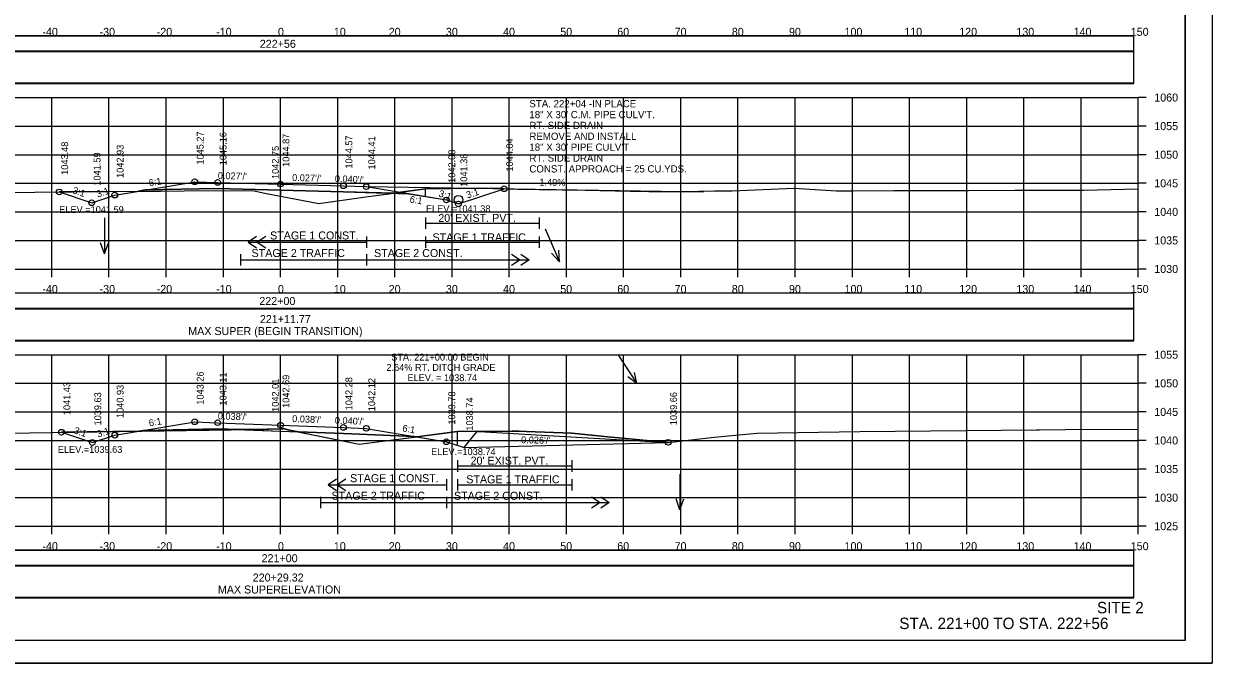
# Model space of a CAD drawing. Extents: x 1370565 to 1374448, y 301010 to 304637.
# Drawn here: x 1373323.9 to 1373531.7, y 303005 to 303116.9 of the extents above; entities that cross this region are included whole.
import ezdxf

# ---------------------------------------------------------------- set-up
doc = ezdxf.new("R2010")
doc.units = 0
for name, color, linetype in [('Default', 7, 'Continuous'), ('R_Alt Surface', 7, 'Continuous'), ('R_Axis', 7, 'Continuous'), ('R_Axis Annot', 7, 'Continuous'), ('R_Border', 7, 'Continuous'), ('R_Contours', 7, 'Continuous'), ('R_Draft', 7, 'Continuous'), ('R_Drive', 7, 'Continuous'), ('R_Exist Surface', 7, 'Continuous'), ('R_Fin Surface', 7, 'Continuous'), ('R_Grid', 7, 'Continuous'), ('R_No Plot', 7, 'Continuous'), ('R_Water', 7, 'Continuous'), ('R_Water Annot', 7, 'Continuous'), ('R_Xsect Elev', 7, 'Continuous'), ('R_Xsect Slope', 7, 'Continuous')]:
    doc.layers.add(name, color=color, linetype=linetype)

msp = doc.modelspace()

# ---------------------------------------------------------------- linework, layer by layer
at = {"layer": 'Default'}
for points in [[(1373219.61, 303112.04), (1373518.02, 303112.04), (1373518.02, 303114.75), (1373219.61, 303114.75)], [(1373219.61, 303106.46), (1373518.02, 303106.46), (1373518.02, 303111.99), (1373219.61, 303111.99)], [(1373219.61, 303067.04), (1373518.02, 303067.04), (1373518.02, 303069.75), (1373219.61, 303069.75)], [(1373219.61, 303061.46), (1373518.02, 303061.46), (1373518.02, 303066.99), (1373219.61, 303066.99)], [(1373219.61, 303022.04), (1373518.02, 303022.04), (1373518.02, 303024.75), (1373219.61, 303024.75)], [(1373219.61, 303016.46), (1373518.02, 303016.46), (1373518.02, 303021.99), (1373219.61, 303021.99)]]:
    msp.add_lwpolyline(points, close=True, dxfattribs=at)
at = {"layer": 'R_Alt Surface'}
for points in [[(1373345.15, 303087.83), (1373357.81, 303088.08), (1373368.81, 303087.78), (1373379.81, 303087.49), (1373391.18, 303087.18)], [(1373364.62, 303079.69), (1373363.12, 303078.69), (1373364.62, 303077.69)], [(1373366.22, 303079.69), (1373364.72, 303078.69), (1373366.22, 303077.69)], [(1373363.12, 303078.69), (1373383.82, 303078.69)], [(1373361.82, 303076.62), (1373361.82, 303074.62)], [(1373361.82, 303075.62), (1373383.82, 303075.62)], [(1373383.82, 303076.62), (1373383.82, 303074.62)], [(1373383.82, 303076.62), (1373383.82, 303074.62)], [(1373383.82, 303075.62), (1373412.31, 303075.62)], [(1373409.22, 303076.62), (1373410.72, 303075.62), (1373409.22, 303074.62)], [(1373410.81, 303076.62), (1373412.31, 303075.62), (1373410.81, 303074.62)], [(1373344.85, 303045.77), (1373357.81, 303046.03), (1373368.81, 303045.61), (1373379.81, 303045.19), (1373392.17, 303044.72)], [(1373378.61, 303037.23), (1373377.11, 303036.23), (1373378.61, 303035.23)], [(1373377.11, 303036.23), (1373397.81, 303036.23)], [(1373380.21, 303037.23), (1373378.71, 303036.23), (1373380.21, 303035.23)], [(1373375.81, 303034.15), (1373375.81, 303032.15)], [(1373397.81, 303034.15), (1373397.81, 303032.15)], [(1373397.81, 303034.15), (1373397.81, 303032.15)], [(1373423.21, 303034.15), (1373424.71, 303033.15), (1373423.21, 303032.15)], [(1373424.8, 303034.15), (1373426.3, 303033.15), (1373424.8, 303032.15)], [(1373375.81, 303033.15), (1373397.81, 303033.15)], [(1373397.81, 303033.15), (1373426.3, 303033.15)]]:
    msp.add_lwpolyline(points, dxfattribs=at)
at = {"layer": 'R_Axis'}
for p, q in [((1373518.81, 303074), (1373518.81, 303104)), ((1373520.21, 303104), (1373518.81, 303104)), ((1373520.21, 303099), (1373518.81, 303099)), ((1373520.21, 303094), (1373518.81, 303094)), ((1373520.21, 303089), (1373518.81, 303089)), ((1373520.21, 303084), (1373518.81, 303084)), ((1373520.21, 303079), (1373518.81, 303079)), ((1373218.81, 303074), (1373518.81, 303074)), ((1373328.81, 303072.6), (1373328.81, 303074)), ((1373338.81, 303072.6), (1373338.81, 303074)), ((1373348.81, 303072.6), (1373348.81, 303074)), ((1373358.81, 303072.6), (1373358.81, 303074)), ((1373368.81, 303072.6), (1373368.81, 303074)), ((1373378.81, 303072.6), (1373378.81, 303074)), ((1373388.81, 303072.6), (1373388.81, 303074)), ((1373398.81, 303072.6), (1373398.81, 303074)), ((1373408.81, 303072.6), (1373408.81, 303074)), ((1373418.81, 303072.6), (1373418.81, 303074)), ((1373428.81, 303072.6), (1373428.81, 303074)), ((1373438.81, 303072.6), (1373438.81, 303074)), ((1373448.81, 303072.6), (1373448.81, 303074)), ((1373458.81, 303072.6), (1373458.81, 303074)), ((1373468.81, 303072.6), (1373468.81, 303074)), ((1373478.81, 303072.6), (1373478.81, 303074)), ((1373488.81, 303072.6), (1373488.81, 303074)), ((1373498.81, 303072.6), (1373498.81, 303074)), ((1373508.81, 303072.6), (1373508.81, 303074)), ((1373518.81, 303072.6), (1373518.81, 303074)), ((1373520.21, 303074), (1373518.81, 303074)), ((1373518.81, 303029), (1373518.81, 303059)), ((1373520.21, 303059), (1373518.81, 303059)), ((1373520.21, 303054), (1373518.81, 303054)), ((1373520.21, 303049), (1373518.81, 303049)), ((1373520.21, 303044), (1373518.81, 303044)), ((1373520.21, 303039), (1373518.81, 303039)), ((1373520.21, 303034), (1373518.81, 303034)), ((1373218.81, 303029), (1373518.81, 303029)), ((1373328.81, 303027.6), (1373328.81, 303029)), ((1373338.81, 303027.6), (1373338.81, 303029)), ((1373348.81, 303027.6), (1373348.81, 303029)), ((1373358.81, 303027.6), (1373358.81, 303029)), ((1373368.81, 303027.6), (1373368.81, 303029)), ((1373378.81, 303027.6), (1373378.81, 303029)), ((1373388.81, 303027.6), (1373388.81, 303029)), ((1373398.81, 303027.6), (1373398.81, 303029)), ((1373408.81, 303027.6), (1373408.81, 303029)), ((1373418.81, 303027.6), (1373418.81, 303029)), ((1373428.81, 303027.6), (1373428.81, 303029)), ((1373438.81, 303027.6), (1373438.81, 303029)), ((1373448.81, 303027.6), (1373448.81, 303029)), ((1373458.81, 303027.6), (1373458.81, 303029)), ((1373468.81, 303027.6), (1373468.81, 303029)), ((1373478.81, 303027.6), (1373478.81, 303029)), ((1373488.81, 303027.6), (1373488.81, 303029)), ((1373498.81, 303027.6), (1373498.81, 303029)), ((1373508.81, 303027.6), (1373508.81, 303029)), ((1373518.81, 303027.6), (1373518.81, 303029)), ((1373520.21, 303029), (1373518.81, 303029))]:
    msp.add_line(p, q, dxfattribs=at)
for points in [[(1373394.16, 303083.01), (1373394.16, 303081.01)], [(1373394.16, 303082.01), (1373414.03, 303082.01)], [(1373414.03, 303083.01), (1373414.03, 303081.01)], [(1373383.82, 303079.69), (1373383.82, 303077.69)], [(1373394.16, 303079.69), (1373394.16, 303077.69)], [(1373414.03, 303079.69), (1373414.03, 303077.69)], [(1373394.16, 303078.69), (1373414.03, 303078.69)], [(1373399.73, 303040.54), (1373399.73, 303038.54)], [(1373419.77, 303040.54), (1373419.77, 303038.54)], [(1373399.73, 303039.54), (1373419.77, 303039.54)], [(1373397.81, 303037.23), (1373397.81, 303035.23)], [(1373399.73, 303037.23), (1373399.73, 303035.23)], [(1373399.73, 303036.23), (1373419.77, 303036.23)], [(1373419.77, 303037.23), (1373419.77, 303035.23)]]:
    msp.add_lwpolyline(points, dxfattribs=at)
at = {"layer": 'R_Border'}
for q in [(1373526.99, 303214.46), (1373210.81, 303009)]:
    msp.add_line((1373526.99, 303009), q, dxfattribs=at)
at = {"layer": 'R_Contours'}
for p, q in [((1373343.73, 303087.59), (1373330.11, 303087.48)), ((1373345.15, 303087.83), (1373343.73, 303087.59)), ((1373368.81, 303086.75), (1373368.81, 303087.78)), ((1373379.81, 303087.49), (1373368.81, 303087.78)), ((1373368.81, 303087.78), (1373368.81, 303086.75)), ((1373388.6, 303087.25), (1373379.81, 303087.49)), ((1373389.8, 303087.42), (1373388.6, 303087.25)), ((1373389.8, 303087.42), (1373391.18, 303087.18)), ((1373391.18, 303087.18), (1373389.8, 303087.42)), ((1373394.16, 303086.69), (1373394.16, 303088.01)), ((1373407.92, 303088.05), (1373407.41, 303088.06)), ((1373388.6, 303087.25), (1373391.18, 303087.18)), ((1373391.18, 303087.18), (1373391.18, 303087.18)), ((1373391.18, 303087.18), (1373397.81, 303086.08)), ((1373344.02, 303045.63), (1373361.46, 303045.89)), ((1373361.46, 303045.89), (1373368.81, 303045.61)), ((1373344.02, 303045.63), (1373330.49, 303045.43)), ((1373344.85, 303045.77), (1373344.02, 303045.63)), ((1373368.81, 303045.61), (1373371.98, 303045.49)), ((1373392.66, 303044.64), (1373392.17, 303044.72)), ((1373392.66, 303044.64), (1373397.81, 303043.78)), ((1373397.81, 303043.78), (1373400.94, 303042.74)), ((1373399.73, 303043.15), (1373399.73, 303045.54)), ((1373400.94, 303042.74), (1373436.58, 303043.67))]:
    msp.add_line(p, q, dxfattribs=at)
for points in [[(1373330.11, 303087.48), (1373335.78, 303085.59), (1373339.81, 303086.94), (1373343.73, 303087.59)], [(1373343.73, 303087.59), (1373351.96, 303087.66), (1373363.89, 303087.74), (1373366.08, 303087.29), (1373368.81, 303086.75)], [(1373368.81, 303087.78), (1373357.81, 303088.08), (1373345.15, 303087.83)], [(1373403.38, 303088.12), (1373398.46, 303088.06), (1373394.16, 303088.01), (1373389.8, 303087.42)], [(1373397.81, 303086.08), (1373399.92, 303085.38), (1373407.92, 303088.05)], [(1373407.41, 303088.06), (1373404.58, 303088.1), (1373403.38, 303088.12)], [(1373368.81, 303086.75), (1373375.48, 303085.44), (1373383.74, 303086.6), (1373388.6, 303087.25)], [(1373391.18, 303087.18), (1373391.18, 303087.18)], [(1373361.46, 303045.89), (1373357.81, 303046.03), (1373344.85, 303045.77)], [(1373371.98, 303045.49), (1373370.36, 303045.82), (1373369.42, 303046.02), (1373368.81, 303046.01), (1373364.11, 303045.93), (1373361.46, 303045.89)], [(1373330.49, 303045.43), (1373335.9, 303043.63), (1373339.81, 303044.93), (1373344.02, 303045.63)], [(1373392.17, 303044.72), (1373379.81, 303045.19), (1373371.98, 303045.49)], [(1373371.98, 303045.49), (1373382.54, 303043.38), (1373392.66, 303044.64)], [(1373436.58, 303043.67), (1373426.02, 303044.66), (1373419.77, 303045.27), (1373411.75, 303045.58), (1373410.49, 303045.63), (1373409.3, 303045.62), (1373399.73, 303045.54), (1373397.05, 303045.19), (1373392.66, 303044.64)]]:
    msp.add_lwpolyline(points, dxfattribs=at)
at = {"layer": 'R_Drive'}
for p, q in [((1373383.82, 303088.41), (1373442.85, 303087.53)), ((1373397.81, 303043.78), (1373400.94, 303042.74))]:
    msp.add_line(p, q, dxfattribs=at)
for points in [[(1373219.61, 303112.1), (1373518.02, 303112.1), (1373518.02, 303114.8), (1373219.61, 303114.8)], [(1373219.61, 303106.57), (1373518.02, 303106.57), (1373518.02, 303112.1), (1373219.61, 303112.1)], [(1373219.61, 303067.1), (1373518.02, 303067.1), (1373518.02, 303069.8), (1373219.61, 303069.8)], [(1373219.61, 303061.57), (1373518.02, 303061.57), (1373518.02, 303067.1), (1373219.61, 303067.1)], [(1373219.61, 303022.1), (1373518.02, 303022.1), (1373518.02, 303024.8), (1373219.61, 303024.8)], [(1373219.61, 303016.57), (1373518.02, 303016.57), (1373518.02, 303022.1), (1373219.61, 303022.1)]]:
    msp.add_lwpolyline(points, close=True, dxfattribs=at)
at = {"layer": 'R_Exist Surface'}
for points in [[(1373306.17, 303087.29), (1373351.96, 303087.66), (1373363.89, 303087.74), (1373366.08, 303087.29), (1373375.48, 303085.44), (1373383.74, 303086.6), (1373394.16, 303088.01), (1373398.46, 303088.06), (1373404.58, 303088.13), (1373410.24, 303087.98), (1373414.03, 303087.89), (1373422.09, 303087.79), (1373429.97, 303087.62), (1373436.46, 303087.53), (1373444.73, 303087.66), (1373447.81, 303087.66), (1373458.57, 303088.14), (1373466.01, 303087.69), (1373468.94, 303087.7), (1373476.06, 303087.72), (1373489.12, 303087.75), (1373497.21, 303087.78), (1373509.21, 303087.81), (1373518.81, 303088.04)], [(1373317.03, 303045.23), (1373364.11, 303045.93), (1373369.42, 303046.02), (1373370.36, 303045.82), (1373382.54, 303043.38), (1373397.05, 303045.19), (1373399.73, 303045.54), (1373409.3, 303045.62), (1373410.49, 303045.63), (1373411.75, 303045.58), (1373419.77, 303045.27), (1373426.02, 303044.66), (1373436.58, 303043.67), (1373444.66, 303044.56), (1373452.09, 303045.3), (1373470.09, 303045.54), (1373501.03, 303045.86), (1373501.53, 303045.84), (1373506.07, 303045.91), (1373518.81, 303045.97)]]:
    msp.add_lwpolyline(points, dxfattribs=at)
at = {"layer": 'R_Fin Surface'}
for points in [[(1373330.11, 303087.48), (1373335.78, 303085.59), (1373339.81, 303086.94), (1373353.81, 303089.27), (1373357.81, 303089.16), (1373368.81, 303088.87), (1373379.81, 303088.57), (1373383.81, 303088.41), (1373397.81, 303086.08), (1373399.92, 303085.38), (1373407.92, 303088.05)], [(1373330.49, 303045.43), (1373335.9, 303043.63), (1373339.81, 303044.93), (1373353.81, 303047.27), (1373357.81, 303047.11), (1373368.81, 303046.7), (1373379.81, 303046.28), (1373383.81, 303046.12), (1373397.81, 303043.78), (1373400.94, 303042.74), (1373403.13, 303045.53), (1373403.14, 303045.55), (1373403.36, 303045.56), (1373403.38, 303045.55), (1373403.56, 303045.54), (1373436.58, 303043.67)]]:
    msp.add_lwpolyline(points, dxfattribs=at)
at = {"layer": 'R_Grid'}
for p, q in [((1373218.81, 303104), (1373518.81, 303104)), ((1373328.81, 303074), (1373328.81, 303104)), ((1373338.81, 303074), (1373338.81, 303104)), ((1373348.81, 303074), (1373348.81, 303104)), ((1373358.81, 303074), (1373358.81, 303104)), ((1373368.81, 303074), (1373368.81, 303104)), ((1373378.81, 303074), (1373378.81, 303104)), ((1373388.81, 303074), (1373388.81, 303104)), ((1373398.81, 303074), (1373398.81, 303104)), ((1373408.81, 303074), (1373408.81, 303104)), ((1373418.81, 303074), (1373418.81, 303104)), ((1373428.81, 303074), (1373428.81, 303104)), ((1373438.81, 303074), (1373438.81, 303104)), ((1373448.81, 303074), (1373448.81, 303104)), ((1373458.81, 303074), (1373458.81, 303104)), ((1373468.81, 303074), (1373468.81, 303104)), ((1373478.81, 303074), (1373478.81, 303104)), ((1373488.81, 303074), (1373488.81, 303104)), ((1373498.81, 303074), (1373498.81, 303104)), ((1373508.81, 303074), (1373508.81, 303104)), ((1373518.81, 303074), (1373518.81, 303104)), ((1373218.81, 303099), (1373518.81, 303099)), ((1373218.81, 303094), (1373518.81, 303094)), ((1373218.81, 303089), (1373518.81, 303089)), ((1373218.81, 303084), (1373518.81, 303084)), ((1373218.81, 303079), (1373518.81, 303079)), ((1373218.81, 303074), (1373518.81, 303074)), ((1373218.81, 303059), (1373518.81, 303059)), ((1373328.81, 303029), (1373328.81, 303059)), ((1373338.81, 303029), (1373338.81, 303059)), ((1373348.81, 303029), (1373348.81, 303059)), ((1373358.81, 303029), (1373358.81, 303059)), ((1373368.81, 303029), (1373368.81, 303059)), ((1373378.81, 303029), (1373378.81, 303059)), ((1373388.81, 303029), (1373388.81, 303059)), ((1373398.81, 303029), (1373398.81, 303059)), ((1373408.81, 303029), (1373408.81, 303059)), ((1373418.81, 303029), (1373418.81, 303059)), ((1373428.81, 303029), (1373428.81, 303059)), ((1373438.81, 303029), (1373438.81, 303059)), ((1373448.81, 303029), (1373448.81, 303059)), ((1373458.81, 303029), (1373458.81, 303059)), ((1373468.81, 303029), (1373468.81, 303059)), ((1373478.81, 303029), (1373478.81, 303059)), ((1373488.81, 303029), (1373488.81, 303059)), ((1373498.81, 303029), (1373498.81, 303059)), ((1373508.81, 303029), (1373508.81, 303059)), ((1373518.81, 303029), (1373518.81, 303059)), ((1373218.81, 303054), (1373518.81, 303054)), ((1373218.81, 303049), (1373518.81, 303049)), ((1373218.81, 303044), (1373518.81, 303044)), ((1373218.81, 303039), (1373518.81, 303039)), ((1373218.81, 303034), (1373518.81, 303034)), ((1373218.81, 303029), (1373518.81, 303029))]:
    msp.add_line(p, q, dxfattribs=at)
at = {"layer": 'R_No Plot'}
msp.add_line((1373198.41, 303005.02), (1373531.75, 303005.02), dxfattribs=at)
for points in [[(1373198.41, 303218.36), (1373531.75, 303218.36), (1373531.75, 303005.02), (1373198.41, 303005.02)], [(1373444.73, 303214.46), (1373464.35, 303214.46), (1373464.35, 303204.58), (1373480.47, 303204.58), (1373503.67, 303204.58), (1373503.67, 303180.25), (1373526.99, 303180.25), (1373526.99, 303009), (1373210.81, 303009), (1373210.81, 303214.46)]]:
    msp.add_lwpolyline(points, close=True, dxfattribs=at)
for centre in [(1373353.81, 303089.27), (1373357.81, 303089.16), (1373330.11, 303087.48), (1373339.81, 303086.94), (1373368.81, 303088.87), (1373379.81, 303088.57), (1373383.81, 303088.41), (1373407.92, 303088.05), (1373335.78, 303085.59), (1373397.81, 303086.08), (1373399.92, 303085.38), (1373330.49, 303045.43), (1373353.81, 303047.27), (1373357.81, 303047.11), (1373368.81, 303046.7), (1373379.81, 303046.28), (1373383.81, 303046.12), (1373335.9, 303043.63), (1373339.81, 303044.93), (1373397.81, 303043.78), (1373436.58, 303043.67)]:
    msp.add_circle(centre, 0.5, dxfattribs=at)
at = {"layer": 'R_Water'}
msp.add_circle((1373399.92, 303086.13), 0.75, dxfattribs=at)
at = {"layer": 'R_Water Annot'}
for p, q in [((1373338.03, 303082.94), (1373338.03, 303076.66)), ((1373415.09, 303081.04), (1373417.61, 303075.28)), ((1373338.03, 303076.66), (1373337.33, 303078.58)), ((1373338.03, 303076.66), (1373338.73, 303078.58)), ((1373417.61, 303075.28), (1373417.48, 303077.32)), ((1373417.61, 303075.28), (1373416.2, 303076.76)), ((1373427.78, 303059.03), (1373431.14, 303053.95)), ((1373431.14, 303053.95), (1373429.52, 303055.14)), ((1373431.14, 303053.95), (1373430.7, 303055.87)), ((1373438.65, 303038.13), (1373438.65, 303031.85)), ((1373438.65, 303031.85), (1373437.97, 303033.77)), ((1373438.65, 303031.85), (1373439.34, 303033.77))]:
    msp.add_line(p, q, dxfattribs=at)
at = {"layer": 'R_Xsect Elev'}
for p, q in [((1373368.81, 303086.75), (1373368.81, 303096.75)), ((1373368.81, 303046.01), (1373368.81, 303056.01))]:
    msp.add_line(p, q, dxfattribs=at)

# ---------------------------------------------------------------- texts
at = {"layer": 'R_Axis Annot'}
for s, p in [('-40', (1373327.16, 303114.8)), ('-30', (1373337.16, 303114.8)), ('-20', (1373347.16, 303114.8)), ('-10', (1373357.55, 303114.8)), ('0', (1373368.36, 303114.8)), ('10', (1373378.13, 303114.8)), ('20', (1373387.73, 303114.8)), ('30', (1373397.73, 303114.8)), ('40', (1373407.73, 303114.8)), ('50', (1373417.73, 303114.8)), ('60', (1373427.7, 303114.8)), ('70', (1373437.73, 303114.8)), ('80', (1373447.73, 303114.8)), ('90', (1373457.73, 303114.8)), ('100', (1373467.44, 303114.8)), ('110', (1373477.89, 303114.8)), ('120', (1373487.5, 303114.8)), ('130', (1373497.5, 303114.8)), ('140', (1373507.5, 303114.8)), ('150', (1373517.5, 303114.8)), ('222+56', (1373365.18, 303112.7)), ('1060', (1373521.61, 303103.3)), ('1055', (1373521.61, 303098.3)), ('1050', (1373521.61, 303093.3)), ('1045', (1373521.61, 303088.3)), ("20' EXIST. PVT.", (1373396.4, 303082.24)), ('1040', (1373521.61, 303083.3)), ('1035', (1373521.61, 303078.3)), ('1030', (1373521.61, 303073.3)), ('-40', (1373327.16, 303069.8)), ('-30', (1373337.16, 303069.8)), ('-20', (1373347.16, 303069.8)), ('-10', (1373357.55, 303069.8)), ('0', (1373368.36, 303069.8)), ('10', (1373378.13, 303069.8)), ('20', (1373387.73, 303069.8)), ('30', (1373397.73, 303069.8)), ('40', (1373407.73, 303069.8)), ('50', (1373417.73, 303069.8)), ('60', (1373427.7, 303069.8)), ('70', (1373437.73, 303069.8)), ('80', (1373447.73, 303069.8)), ('90', (1373457.73, 303069.8)), ('100', (1373467.44, 303069.8)), ('110', (1373477.89, 303069.8)), ('120', (1373487.5, 303069.8)), ('130', (1373497.5, 303069.8)), ('140', (1373507.5, 303069.8)), ('150', (1373517.5, 303069.8)), ('222+00', (1373365.1, 303067.7)), ('221+11.77', (1373365.2, 303064.54)), ('MAX SUPER (BEGIN TRANSITION)', (1373352.67, 303062.44)), ('1055', (1373521.61, 303058.3)), ('1050', (1373521.61, 303053.3)), ('1045', (1373521.61, 303048.3)), ('1040', (1373521.61, 303043.3)), ("20' EXIST. PVT.", (1373402.05, 303039.77)), ('1035', (1373521.61, 303038.3)), ('1030', (1373521.61, 303033.3)), ('1025', (1373521.61, 303028.3)), ('-40', (1373327.16, 303024.8)), ('-30', (1373337.16, 303024.8)), ('-20', (1373347.16, 303024.8)), ('-10', (1373357.55, 303024.8)), ('0', (1373368.36, 303024.8)), ('10', (1373378.13, 303024.8)), ('20', (1373387.73, 303024.8)), ('30', (1373397.73, 303024.8)), ('40', (1373407.73, 303024.8)), ('50', (1373417.73, 303024.8)), ('60', (1373427.7, 303024.8)), ('70', (1373437.73, 303024.8)), ('80', (1373447.73, 303024.8)), ('90', (1373457.73, 303024.8)), ('100', (1373467.44, 303024.8)), ('110', (1373477.89, 303024.8)), ('120', (1373487.5, 303024.8)), ('130', (1373497.5, 303024.8)), ('140', (1373507.5, 303024.8)), ('150', (1373517.5, 303024.8)), ('221+00', (1373365.5, 303022.7)), ('220+29.32', (1373363.95, 303019.32)), ('MAX SUPERELEVATION', (1373357.85, 303017.22))]:
    msp.add_text(s, height=1.4, dxfattribs=at).set_placement(p)
at = {"layer": 'R_Draft'}
for s, p in [('SITE 2', (1373511.59, 303013.76)), ('STA. 221+00 TO STA. 222+56', (1373477.02, 303011))]:
    msp.add_text(s, height=2, dxfattribs=at).set_placement(p)
at = {"layer": 'R_Water'}
for s, p in [('STAGE 1 CONST.', (1373366.98, 303079.17)), ('STAGE 1 TRAFFIC', (1373395.39, 303078.84)), ('STAGE 2 TRAFFIC', (1373363.74, 303076.1)), ('STAGE 2 CONST.', (1373385.16, 303076.09)), ('STAGE 1 CONST.', (1373380.97, 303036.7)), ('STAGE 1 TRAFFIC', (1373401.29, 303036.5)), ('STAGE 2 TRAFFIC', (1373377.73, 303033.63)), ('STAGE 2 CONST.', (1373399.15, 303033.62))]:
    msp.add_text(s, height=1.4, dxfattribs=at).set_placement(p)
at = {"layer": 'R_Water Annot'}
for s, p in [('STA. 222+04 -IN PLACE ', (1373412.33, 303102.29)), ('18" X 30\' C.M. PIPE CULV\'T.', (1373412.33, 303100.39)), ('RT. SIDE DRAIN', (1373412.33, 303098.49)), ('REMOVE AND INSTALL', (1373412.33, 303096.59)), ('18" X 30\' PIPE CULV\'T', (1373412.33, 303094.69)), ('RT. SIDE DRAIN', (1373412.33, 303092.79)), ('CONST. APPROACH = 25 CU.YDS.', (1373412.33, 303090.89))]:
    msp.add_text(s, height=1.2661, dxfattribs=at).set_placement(p)
at = {"layer": 'R_Xsect Elev'}
for s, rotation, p in [('1045.27', 90, (1373355.36, 303092.27)), ('1045.16', 90, (1373359.36, 303092.16)), ('1043.48', 90, (1373331.66, 303090.48)), ('1044.87', 90, (1373370.36, 303091.87)), ('1044.57', 90, (1373381.36, 303091.57)), ('1044.41', 90, (1373385.36, 303091.41)), ('1044.04', 90, (1373409.47, 303091.05)), ('1041.59', 90, (1373337.33, 303088.59)), ('1042.93', 90, (1373341.36, 303089.94)), ('1042.75', 90, (1373368.51, 303089.75)), ('1042.08', 90, (1373399.36, 303089.08)), ('1041.38', 90, (1373401.47, 303088.38)), ('1.49%', 359.1478, (1373414.07, 303088.6)), ('1041.43', 90, (1373332.04, 303048.43)), ('1043.26', 90, (1373355.36, 303050.27)), ('1043.11', 90, (1373359.36, 303050.11)), ('1042.01', 90, (1373368.51, 303049.01)), ('1042.69', 90, (1373370.36, 303049.7)), ('1042.28', 90, (1373381.36, 303049.28)), ('1042.12', 90, (1373385.36, 303049.12)), ('1039.63', 90, (1373337.45, 303046.63)), ('1040.93', 90, (1373341.36, 303047.93)), ('1039.78', 90, (1373399.36, 303046.78)), ('1039.66', 90, (1373438.13, 303046.67)), ('1038.74', 90, (1373402.48, 303045.72))]:
    msp.add_text(s, height=1.2, rotation=rotation, dxfattribs=at).set_placement(p)
for s, p in [('ELEV.=1041.59', (1373330.1, 303083.79)), ('ELEV.=1041.38', (1373394.24, 303083.95)), ('STA. 221+00.00 BEGIN ', (1373388.16, 303057.98)), ('2.64% RT. DITCH GRADE', (1373387.32, 303056.18)), ('ELEV. = 1038.74', (1373391.01, 303054.38)), ('ELEV.=1039.63', (1373329.86, 303041.83)), ('ELEV.=1038.74', (1373395.14, 303041.44))]:
    msp.add_text(s, height=1.2, dxfattribs=at).set_placement(p)
at = {"layer": 'R_Xsect Slope'}
for s, rotation, p in [('6:1', 9.4623, (1373345.88, 303088.46)), ("0.027'/'", 358.4634, (1373357.82, 303089.76)), ("0.027'/'", 358.4634, (1373370.82, 303089.41)), ("0.040'/'", 357.7094, (1373378.28, 303089.23)), ('3:1', 341.5668, (1373332.32, 303087.28)), ('3:1', 18.4349, (1373336.85, 303086.48)), ('3:1', 341.5651, (1373396.36, 303086.73)), ('3:1', 18.4332, (1373401.51, 303086.33)), ('6:1', 350.5377, (1373391.33, 303085.66)), ('6:1', 9.4623, (1373345.88, 303046.45)), ("0.038'/'", 357.8238, (1373357.82, 303047.71)), ("0.038'/'", 357.8238, (1373370.82, 303047.22)), ("0.040'/'", 357.7094, (1373378.28, 303046.94)), ('3:1', 341.5668, (1373332.57, 303045.27)), ('3:1', 18.4349, (1373336.91, 303044.49)), ('6:1', 350.5377, (1373390.05, 303045.59)), ("0.026'/'", 358.8542, (1373410.87, 303043.52))]:
    msp.add_text(s, height=1.2, rotation=rotation, dxfattribs=at).set_placement(p)

doc.saveas('drawing.dxf')
